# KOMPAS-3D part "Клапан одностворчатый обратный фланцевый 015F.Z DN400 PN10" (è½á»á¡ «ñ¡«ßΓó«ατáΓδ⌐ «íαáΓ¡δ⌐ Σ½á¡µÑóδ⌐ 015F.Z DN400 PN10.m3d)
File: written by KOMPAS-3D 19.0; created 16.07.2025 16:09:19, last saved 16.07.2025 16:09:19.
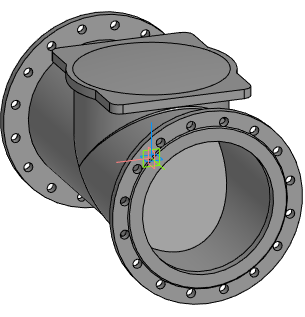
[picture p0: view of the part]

Document properties: Полное имя файла: E:\Dendor Работа Сачек\3D для проектировщиков\5.4 Тип 015F.Z. Клапан одностворчатый обратный фланцевый\stp_Клапан одностворчатый обратный фланцевый 015F.Z PN10_16\Клапан одностворчатый обратный фланцевый 015F.Z DN400 PN10.m3d

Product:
- Part/product: Клапан одностворчатый обратный фланцевый 015F.Z DN400 PN10

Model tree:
1. Операция без истории:1  (labels: Клапан одностворчатый обратный фланцевый 015F.Z DN400 PN10)
2. Операция без истории:2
